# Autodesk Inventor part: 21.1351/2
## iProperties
Created: 2006-12
Part Number: 21.1351/2
Document SubType Name: Modeling
Designer: Andy Moles
Material: Steel, Mild
Density: 7.86 g/cm^3
Mass: 4.25424 g
Surface Area: 8.34272 cm^2
Volume: 0.541252 cm^3
Description: M8 SQUARE NUT POS FXG
Vendor: S
Author: Andy Moles
Title: M8 SQUARE NUT POS FXG
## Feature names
1. Extrusion1
2. Revolution1
3. Fillet2
4. Extrusion3
